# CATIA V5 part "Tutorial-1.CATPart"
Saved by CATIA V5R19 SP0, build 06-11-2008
Part number: Part1
Bounding box of the stored display mesh (mm): x -20 to 20, y -95 to 0, z 0 to 40
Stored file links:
  D:\Shriniwas\v5_r19\Part files\c05\c05tut1.CATPart
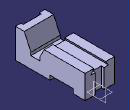
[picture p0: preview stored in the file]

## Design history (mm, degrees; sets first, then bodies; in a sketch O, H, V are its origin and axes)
Body1 (main body)
  Sketch1 on yz-plane, origin (0, 0, 0), H (0, 1, 0), V (0, 0, 1)
    line L1 (0, 0) -> (-16, 0)
    line L2 (-16, 0) -> (-16, 6)
    line L3 (-16, 6) -> (-48, 6)
    line L4 (-48, 6) -> (-48, 0)
    point P4 (-48, 0)
    line L5 (-48, 0) -> (-95, 0)
    line L6 (-95, 0) -> (-95, 40)
    line L7 (-95, 40) -> (-83, 40)
    line L8 (-83, 40) -> (-74, 20)
    line L9 (-74, 20) -> (-74, 16)
    line L10 (-74, 16) -> (-62, 16)
    line L11 (-62, 16) -> (-62, 20)
    point P11 (-62, 20)
    line L12 (-62, 20) -> (-56, 32)
    point P12 (-56, 32)
    line L13 (-56, 32) -> (0, 32)
    point P13 (0, 32)
    line L14 (0, 32) -> (0, 0)
    length L1 = 16
    length L3 = 32
    distance L14 L6 = 95
    length L2 = 6
    length L14 = 32
    length L9 = 4
    distance L5 L10 = 16
    length L7 = 12
    distance L11 P12 = 6
    length L10 = 12
    length L13 = 56
    distance P11 L13 = 12
    length L6 = 40
    horizontal: L1 H, L3 H, L5 H, L7 H, L10 H, L13 H
    vertical: L2 V, L4 V, L6 V, L9 V, L11 V, L14 V
    coincidence: P4 H, P13 V
  Pad1: profile Sketch1, direction (1, 0, 0), length 20, mirrored extent
  Sketch2 on face of Pad1 from Sketch1.L14, origin (0, 0, 0), H (-1, 0, 0), V (0, 0, 1)
    point P1 (-12, 26)
    line L1 (-12, 26) -> (12, 26)
    point P2 (12, 26)
    line L2 (12, 26) -> (8, 32)
    point P3 (8, 32)
    line L3 (8, 32) -> (-8, 32)
    point P4 (-8, 32)
    line L4 (-8, 32) -> (-12, 26)
    reference projected line E1 (20, 32) -> (-20, 32) from edge [face of Pad1 from Sketch1.L13 | face of Pad1 from Sketch1.L14]
    reference projected line E2 (20, 0) -> (20, 32) from edge [start face of Pad1 | face of Pad1 from Sketch1.L14]
    reference projected line E3 (-20, 0) -> (-20, 32) from edge [face of Pad1 from Sketch1.L14 | end face of Pad1]
    reference projected line E4 (-20, 0) -> (-20, 32) from edge [face of Pad1 from Sketch1.L14 | end face of Pad1]
    reference projected line E5 (20, 0) -> (20, 32) from edge [start face of Pad1 | face of Pad1 from Sketch1.L14]
    distance L1 L3 = 6
    distance P3 E2 = 12
    distance P4 E3 = 12
    distance P1 E4 = 8
    distance P2 E5 = 8
    horizontal: L1 H, L3 H
    coincidence: E1 L3
  Pocket1: profile Sketch2, direction (0, -1, 0), through (limit type 6)
  Sketch3 on face of Pad1 from Sketch1.L14, origin (0, 0, 0), H (-1, 0, 0), V (0, 0, 1)
    point P1 (6, 0)
    line L1 (6, 0) -> (-6, 0)
    line L2 (-6, 0) -> (-6, 26)
    line L3 (-6, 26) -> (6, 26)
    line L4 (6, 26) -> (6, 0)
    reference projected line E1 (-12, 26) -> (12, 26) from edge [face of Pad1 from Sketch1.L14 | face of Pocket1 from Sketch2.L1]
    length L1 = 12
    distance V L4 = 6
    coincidence: P1 H, E1 L3
    horizontal: L1 H, L3 H
    vertical: L2 V, L4 V
  Pocket2: profile Sketch3, direction (0, -1, 0), length 4
  Sketch4 on face of Pad1 from Sketch1.L7, origin (0, 0, 40), H (1, 0, 0), V (0, 1, 0)
    line L1 (-12.5, -95) -> (12.5, -95)
    line L2 (12.5, -95) -> (12.5, -92)
    line L3 (12.5, -92) -> (-12.5, -92)
    line L4 (-12.5, -92) -> (-12.5, -95)
    reference projected line E1 (-20, -95) -> (20, -95) from edge [face of Pad1 from Sketch1.L6 | face of Pad1 from Sketch1.L7]
    reference projected line E2 (-20, -83) -> (-20, -95) from edge [start face of Pad1 | face of Pad1 from Sketch1.L7]
    length L1 = 25
    length L4 = 3
    distance L4 E2 = 7.5
    horizontal: L1 H, L3 H
    vertical: L2 V, L4 V
    coincidence: E1 L1
  Pocket3: profile Sketch4, direction (0, 0, -1), through (limit type 3)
